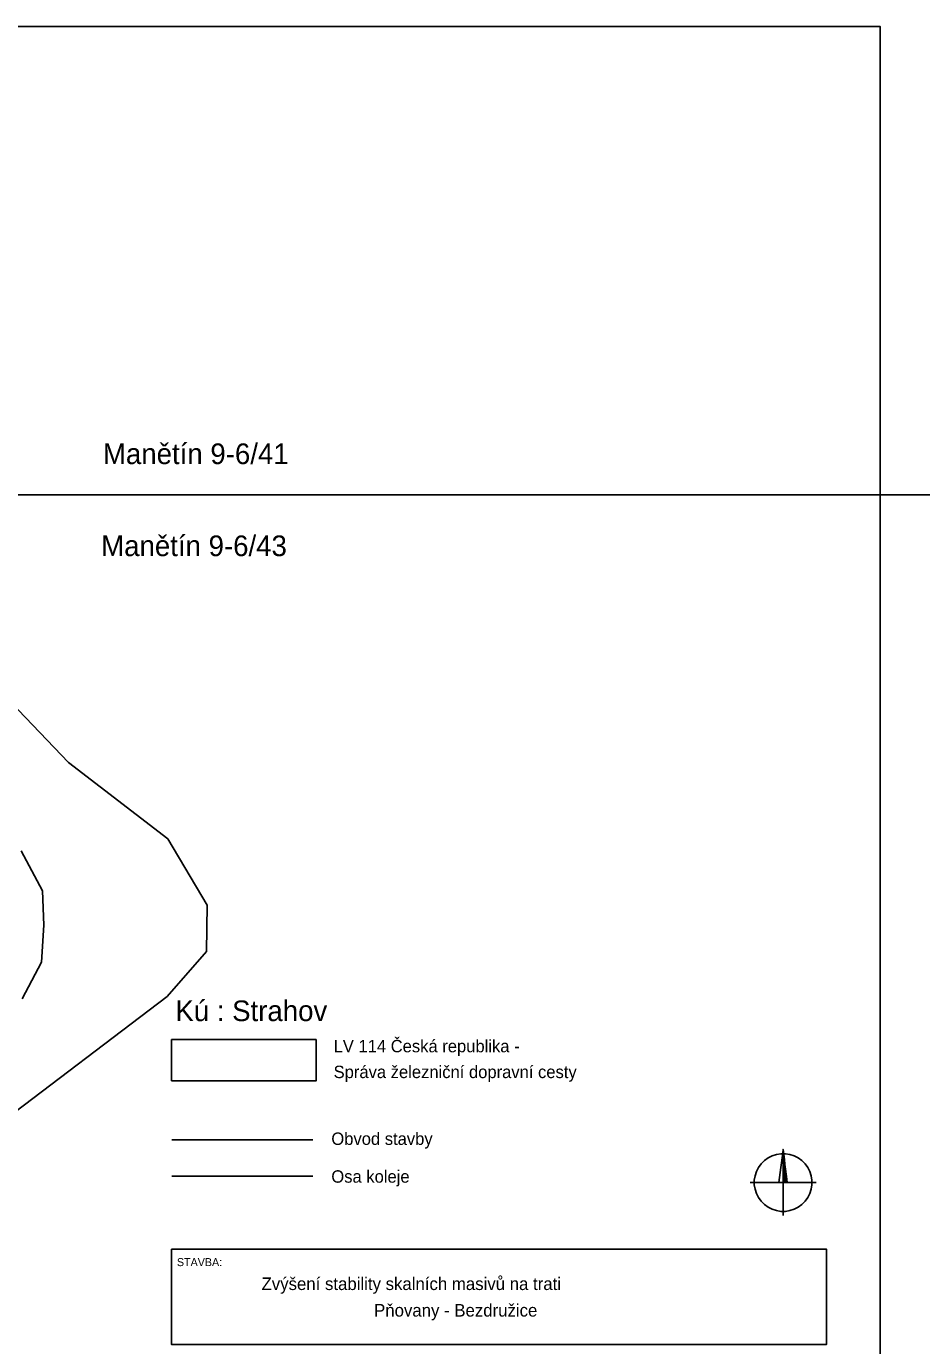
# Model space of a CAD drawing. Extents: x -852001 to -842497, y -1063614 to -1052182.
# Drawn here: x -848701 to -848484.2, y -1053706.1 to -1053386.6 of the extents above; entities that cross this region are included whole.
import ezdxf

# ---------------------------------------------------------------- set-up
doc = ezdxf.new("R2010")
doc.units = 0
for name, color, linetype in [('Default', 7, 'Continuous'), ('KLADY_ZMVM', 7, 'Continuous'), ('KN_HRANICE', 7, 'Continuous'), ('LEGENDA', 7, 'Continuous'), ('tabulka', 7, 'Continuous')]:
    doc.layers.add(name, color=color, linetype=linetype)

# ---------------------------------------------------------------- blocks, each defined once
blk = doc.blocks.new('SEVER')
at = {"layer": 'Default'}
for points in [[(5.5, 69.8), (16.3, 68.1), (26.7, 64.7), (36.5, 59.7), (45.4, 53.2), (53.2, 45.4), (59.7, 36.5), (64.7, 26.7), (68.1, 16.3), (69.8, 5.5), (69.8, -5.5), (68.1, -16.3), (64.7, -26.7), (59.7, -36.5), (53.2, -45.4), (45.4, -53.2), (36.5, -59.7), (26.7, -64.7), (16.3, -68.1), (5.5, -69.8), (-5.5, -69.8), (-16.3, -68.1), (-26.7, -64.7), (-36.5, -59.7), (-45.4, -53.2), (-53.2, -45.4), (-59.7, -36.5), (-64.7, -26.7), (-68.1, -16.3), (-69.8, -5.5), (-69.8, 5.5), (-68.1, 16.3), (-64.7, 26.7), (-59.7, 36.5), (-53.2, 45.4), (-45.4, 53.2), (-36.5, 59.7), (-26.7, 64.7), (-16.3, 68.1), (-5.5, 69.8), (5.5, 69.8)], [(-10, 0), (-8.5, 12), (-7, 24), (-5.5, 36), (-4, 48), (-2.5, 60), (-1, 72), (0, 80), (1.5, 68), (3, 56), (4.5, 44), (6, 32), (7.5, 20), (9, 8), (10, 0), (9.2, 0.8), (9.2, 5.6), (8.4, 12), (8.4, 0.8), (7.6, 0.8), (7.6, 13.5), (7.6, 18.4), (6.8, 24.8), (6.8, 12.1), (6.8, 0.8), (6, 0.8), (6, 13.5), (6, 26.2), (6, 31.2), (5.2, 36.8), (5.2, 24.1), (5.2, 11.4), (5.2, 0.8), (4.4, 0.8), (4.4, 13.5), (4.4, 26.2), (4.4, 38.9), (4.4, 43.2), (3.6, 50.4), (3.6, 37.7), (3.6, 25), (3.6, 12.3), (3.6, 0.8), (2.8, 0.8), (2.8, 13.5), (2.8, 26.2), (2.8, 38.9), (2.8, 51.6), (2.8, 56), (2, 63.2), (2, 50.5), (2, 37.8), (2, 25.1), (2, 12.4), (2, 0.8), (1.2, 0.8), (1.2, 13.5), (1.2, 26.2), (1.2, 38.9), (1.2, 51.6), (1.2, 64.3), (1.2, 69.6), (0.4, 76), (0.4, 63.3), (0.4, 50.6), (0.4, 37.9), (0.4, 25.2), (0.4, 12.5), (0.4, 0.8)], [(0, 80), (0, 67.3), (0, 54.6), (0, 41.9), (0, 29.2), (0, 16.5), (0, 3.8), (0, -8.9), (0, -21.6), (0, -34.3), (0, -47), (0, -59.7), (0, -72.4), (0, -80)], [(80, 0), (67.3, 0), (54.6, 0), (41.9, 0), (29.2, 0), (16.5, 0), (3.8, 0), (-8.9, 0), (-21.6, 0), (-34.3, 0), (-47, 0), (-59.7, 0), (-72.4, 0), (-80, 0)]]:
    blk.add_lwpolyline(points, dxfattribs=at)

msp = doc.modelspace()

# ---------------------------------------------------------------- linework, layer by layer
at = {"layer": 'KLADY_ZMVM'}
msp.add_lwpolyline([(-849375, -1053500), (-848750, -1053500), (-848125, -1053500)], dxfattribs=at)
at = {"layer": 'KN_HRANICE'}
for p, q in [((-848719.8, -1053534.65), (-848690.77, -1053564.81)), ((-848690.77, -1053564.81), (-848666.75, -1053583.37)), ((-848702.23, -1053586.26), (-848697.12, -1053595.94)), ((-848666.75, -1053583.37), (-848657.23, -1053599.4)), ((-848697.12, -1053595.94), (-848696.81, -1053604.27)), ((-848657.23, -1053599.4), (-848657.38, -1053610.65)), ((-848696.81, -1053604.27), (-848697.31, -1053613.24)), ((-848657.38, -1053610.65), (-848666.91, -1053621.5)), ((-848697.31, -1053613.24), (-848702.05, -1053622.12)), ((-848666.91, -1053621.5), (-848755.24, -1053688.54))]:
    msp.add_line(p, q, dxfattribs=at)
at = {"layer": 'LEGENDA'}
for p, q in [((-848665.82, -1053631.92), (-848630.82, -1053631.92)), ((-848665.82, -1053631.92), (-848665.82, -1053641.92)), ((-848665.8, -1053656.2), (-848631.6, -1053656.2)), ((-848665.8, -1053665.03), (-848631.6, -1053665.03))]:
    msp.add_line(p, q, dxfattribs=at)
msp.add_lwpolyline([(-849088.27, -1053806.56), (-848494.27, -1053806.56), (-848494.27, -1053386.56), (-849088.27, -1053386.56)], close=True, dxfattribs=at)
msp.add_lwpolyline([(-848630.82, -1053631.92), (-848630.82, -1053641.92), (-848665.82, -1053641.92)], dxfattribs=at)
at = {"layer": 'tabulka'}
msp.add_lwpolyline([(-848665.89, -1053682.72), (-848507.23, -1053682.72), (-848507.23, -1053705.78), (-848665.89, -1053705.78)], close=True, dxfattribs=at)

# ---------------------------------------------------------------- block references
at = {"layer": 'LEGENDA', "xscale": 0.1, "yscale": 0.10000000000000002}
msp.add_blockref('SEVER', (-848517.74, -1053666.57), dxfattribs=at)

# ---------------------------------------------------------------- texts
at = {"layer": 'KLADY_ZMVM'}
for s, p in [('Manětín 9-6/41', (-848682.46, -1053492.57)), ('Manětín 9-6/43', (-848682.89, -1053514.86))]:
    msp.add_text(s, height=5, dxfattribs=at).set_placement(p)
at = {"layer": 'LEGENDA'}
for s, height, p in [('Kú : Strahov', 5, (-848664.93, -1053627.48)), ('LV 114 Česká republika -', 3, (-848626.6, -1053635.03)), ('Správa železniční dopravní cesty', 3, (-848626.6, -1053641.28)), ('Obvod stavby', 3, (-848627.15, -1053657.46)), ('Osa koleje', 3, (-848627.15, -1053666.61)), ('Zvýšení stability skalních masivů na trati', 3.04, (-848644.05, -1053692.61)), ('Pňovany - Bezdružice', 3.04, (-848616.8, -1053699.04))]:
    msp.add_text(s, height=height, dxfattribs=at).set_placement(p)
at = {"layer": 'tabulka'}
msp.add_text('STAVBA:', height=1.94, dxfattribs=at).set_placement((-848664.55, -1053686.82))

doc.saveas('drawing.dxf')
